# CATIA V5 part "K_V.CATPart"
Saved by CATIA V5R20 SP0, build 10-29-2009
Part number: V
Bounding box of the stored display mesh (mm): x -160 to 160, y -95 to -20, z -160 to 160
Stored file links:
  G:\Khaled_CFAO_2011\ST2M\ST2M_GR1\mponsin\Khaled\CAD_ThinkMOTION\K_V.CATPart
  C:\Users\Socar\Documents\thinkmotion\Final\Diff2.CATProduct
  G:\Khaled_CFAO_2011\ST2M\ST2M_GR1\mponsin\Khaled\CAD_ThinkMOTION\K_mponsin.CATProduct
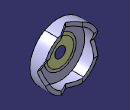
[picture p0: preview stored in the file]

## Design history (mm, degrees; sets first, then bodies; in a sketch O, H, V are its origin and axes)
Parameters
  `Angle de poussée` = 60 deg
External parameters (linked from other documents)
  `External.R interne` = 160 mm
  `External.Rint embrayage` = 70 mm
  External.Lappui = 50 mm
  `External.R appui` = 30 mm
Set1
  Line1: linked copy from another document
  DatumSurface1: linked copy from another document
  Plane1: linked copy from another document
  Plane2 "disques/V": linked copy from another document
  Line2 "axe general": linked copy from another document
  Plane3: linked copy from another document
  DatumCurve1: linked copy from another document
Body1 (main body)
  Sketch1 on yz-plane, origin (0, 0, 0), H (0, 1, 0), V (0, 0, 1)
    line L1 (-95, 75) -> (-85, 75)
    line L2 (-85, 75) -> (-85, 138.9213)
    line L3 (-95, 160) -> (-95, 75)
    point P3 (-95, 160)
    point P4 (-95, 160)
    line L4 (-95, 160) -> (-20, 160)
    line L5 (-20, 160) -> (-20, 138.9213)
    line L6 (-20, 138.9213) -> (-85, 138.9213)
    reference projected line E1 through (0, 0) direction (0, 1) from Line1
    reference intersected line E2 through (-85, 0) direction (0, -1) from face of DatumSurface1
    reference intersected line E3 through (0, 138.9213) direction (1, 0) from Plane1
    reference intersected line E4 through (-95, 0) direction (0, 1) from Plane2
    distance L4 H = 160 {= `External.R interne`}
    distance L1 H = 75 {= `External.Rint embrayage` +5mm}
    distance E1 L5 = 20 {= External.Lappui -`External.R appui`}
    horizontal: L1 H, L4 H, L6 H
    vertical: L2 V, L3 V, L5 V
    coincidence: P3 P4, E2 L2, E3 L6, E4 L3
  Shaft1: profile Sketch1, axis Line2, angle 360
  Sketch2 on Plane3, origin (-160, 0, 0), H (0, -1, 0), V (0, 0, 1)
    line L1 (0, 0) -> (0, 94.641)
    point P1 (0, 94.641)
    line L2 (0, 94.641) -> (54.641, 0)
    point P2 (54.641, 0)
    reference projected line E1 through (0, 0) direction (-1, 0) from Line2
    reference projected line E2 through (0, 0) direction (-1, 0) from Line2
    reference projected arc E3 centre (20, 0) radius 30 from (20, -30) to (20, 30) cw from edge of DatumCurve1
    point P3 (54.641, 0)
    point P4 (0, -94.641)
    line L3 (0, -94.641) -> (54.641, 0)
    point P5 (0, 0)
    line L4 (0, 0) -> (0, -94.641)
    angle L2 E2 = 60 {= `Angle de poussée`}
    vertical: L1 V
    coincidence: E1 P2, O P5, P2 P3
    tangency: L2 E3
    symmetry: P2 P3 H, P1 P4 H, L2 L3 H, O P5 H, L1 L4 H
  Pocket1: profile Sketch2, direction (1, 0, 0), through (limit type 3)
  CircPattern1: of Pocket1, instances 2, angular step 90, axis from Line2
